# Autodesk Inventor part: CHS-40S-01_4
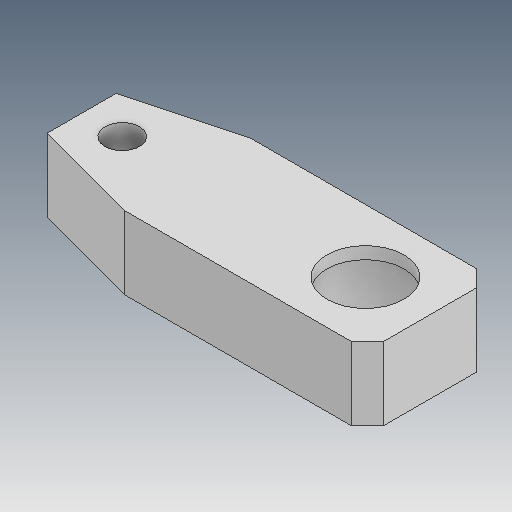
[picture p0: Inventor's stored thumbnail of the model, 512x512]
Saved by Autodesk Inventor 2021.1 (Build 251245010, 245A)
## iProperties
Created: 2019-04
Part Number: CHS-40S-01_4
Material: Ogólny
Document SubType Name: Modeling
Designer: user
Density: 1 g/cm^3
Appearance: Domyślna
Author: user
Revision Number: ÈÎºÎ
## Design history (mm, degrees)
feature "ÊäÈë1"
node "Bryła1"
